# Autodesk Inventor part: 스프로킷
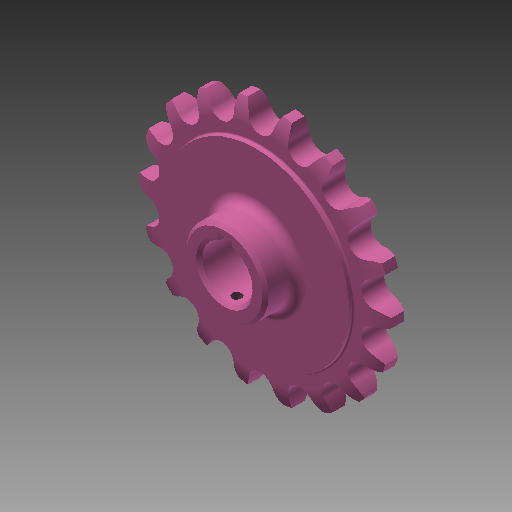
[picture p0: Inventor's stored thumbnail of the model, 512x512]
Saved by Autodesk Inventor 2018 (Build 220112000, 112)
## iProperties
Created: 2016-03
Part Number: 스프로킷
Material: 강철, 탄소
Document SubType Name: Modeling
Designer: mduedu
Density: 7.87 g/cm^3
Mass: 301.818 g
Surface Area: 124.882 cm^2
Volume: 38.3505 cm^3
Appearance: 분홍색
Author: mduedu
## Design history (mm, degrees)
sketch "스케치1"
  geometry: L1 (0, 5)-(29.5, 5); L2 (29.5, 5)-(29.5, 4.1); L3 (30, 3.6)-(33.625, 3.6); L4 (40, 2)-(40, 0); L5 (40, 0)-(0, 0); L6 (0, 0)-(0, 5); L7 (0, -5)-(29.5, -5); L8 (29.5, -5)-(29.5, -4.1); L9 (30, -3.6)-(33.625, -3.6); L10 (40, -2)-(40, 0); L11 (0, 0)-(0, -5); A1 r 13.5 centre (33.625, -9.9) between (40, 2) and (33.625, 3.6); A2 r 13.5 centre (33.625, 9.9) between (33.625, -3.6) and (40, -2); A3 r 0.5 centre (30, 4.1) between (29.5, 4.1) and (30, 3.6); A4 r 0.5 centre (30, -4.1) between (30, -3.6) and (29.5, -4.1); 2 further points
  constraints: 22 end point, 8 point on circle, 6 symmetric about line, 5 tangent, 4 centre point, 4 parallel, 4 point on line, 1 equal radius, 1 horizontal, 1 perpendicular, 1 other
  dimensions: "d0" = 80 diameter of L4 L6; "d2" = 59 diameter of L2 L6; "d3" = 1.6 vertical distance of L4.start L3.end; "d4" = 3.6 distance from line of L4.end L3; "d5" = 5 distance between parallel lines of L5 L1; "d6" = 13.5 radius of A1; "d15" = 0.5 radius of A3
revolve "회전1" sketch "스케치1" stored, may be unused: angle "d7" = 90 deg
sketch "스케치2" dims "d8" = 65.2, "d11" = 80
  geometry: L1 (0, 0)-(0, 32.6); A1 r 36.57 centre (0, 0) between (-16.231, 32.771) and (0, 36.57); A2 r 3.97 centre (0, 36.57) between (-3.866, 35.665) and (0, 32.6); A3 r 12.7 centre (-16.231, 32.771) between (-3.866, 35.665) and (-5.534, 39.615); A4 r 12.7 centre (16.231, 32.771) between (5.534, 39.615) and (3.866, 35.665); A5 r 3.97 centre (0, 36.57) between (0, 32.6) and (3.866, 35.665); A6 r 40 centre (0, 0) between (5.534, 39.615) and (-5.534, 39.615); 2 further points
  constraints: 12 point on circle, 6 centre point, 4 coincident, 3 symmetric about line, 2 end point, 1 point on line, 1 tangent, 1 vertical, 1 vertical alignment, 7 other
  dimensions: "d10" = 73.14 diameter of A1; "d12" = 12.7 radius of A3
extrude "돌출1" cut sketch "스케치2" extent not by distance; stored distance "d13" = 10; taper "d14" = 0 deg
sketch "스케치3"
  geometry: C1 r 13 at (0, 0); 1 further point
  constraints: 1 centre point, 1 coincident
  dimensions: "d19" = 26 diameter of C1
extrude "돌출2" join sketch "스케치3" distance "d20" = 10; taper "d21" = 0 deg
fillet "모깎기1" dims "d22" = 3
sketch "스케치4"
  geometry: L1 (-2.5, 0)-(2.5, 0); L2 (2.5, 0)-(2.5, 10.3); L3 (2.5, 10.3)-(-2.5, 10.3); L4 (-2.5, 10.3)-(-2.5, 0); C1 r 8 at (0, 0); 2 further points
  constraints: 8 end point, 2 coincident, 2 parallel, 1 centre point, 1 horizontal, 1 midpoint, 1 perpendicular
  dimensions: "d23" = 16 diameter of C1; "d25" = 5 distance of L2.end L3.end; "d26" = 10.3 distance of L1.end L2.end
extrude "돌출3" cut sketch "스케치4" extent not by distance; stored distance "d27" = 8; taper "d28" = 0 deg
chamfer "모따기2" distance "d42" = 1; stored, may be unused: second distance "d43" = 2, angle "d44" = 45 deg
node "작업 평면2"
sketch "스케치6"
  geometry: L1 (-12, 15)-(12, 15) reference; 2 further points
  constraints: 1 vertical alignment
  dimensions: "d59" = 4 distance from line of point (0.008, 11) L1
hole "구멍2" sketch "스케치6" at (0.008, 11) diameter "d48" = 3; stored, may be unused: countersink angle "d52" = 90 deg, drill point angle "d54" = 118 deg; dims "d49" = 6, "d50" = 4, "d51" = 2, "d53" = 8
thread "Thread1" dims "d56" = 10, "d57" = 0
node "솔리드1"
pattern_circular "원형 패턴1" dims angle "d17" = 360 deg
other parameters: "d55" = -13
